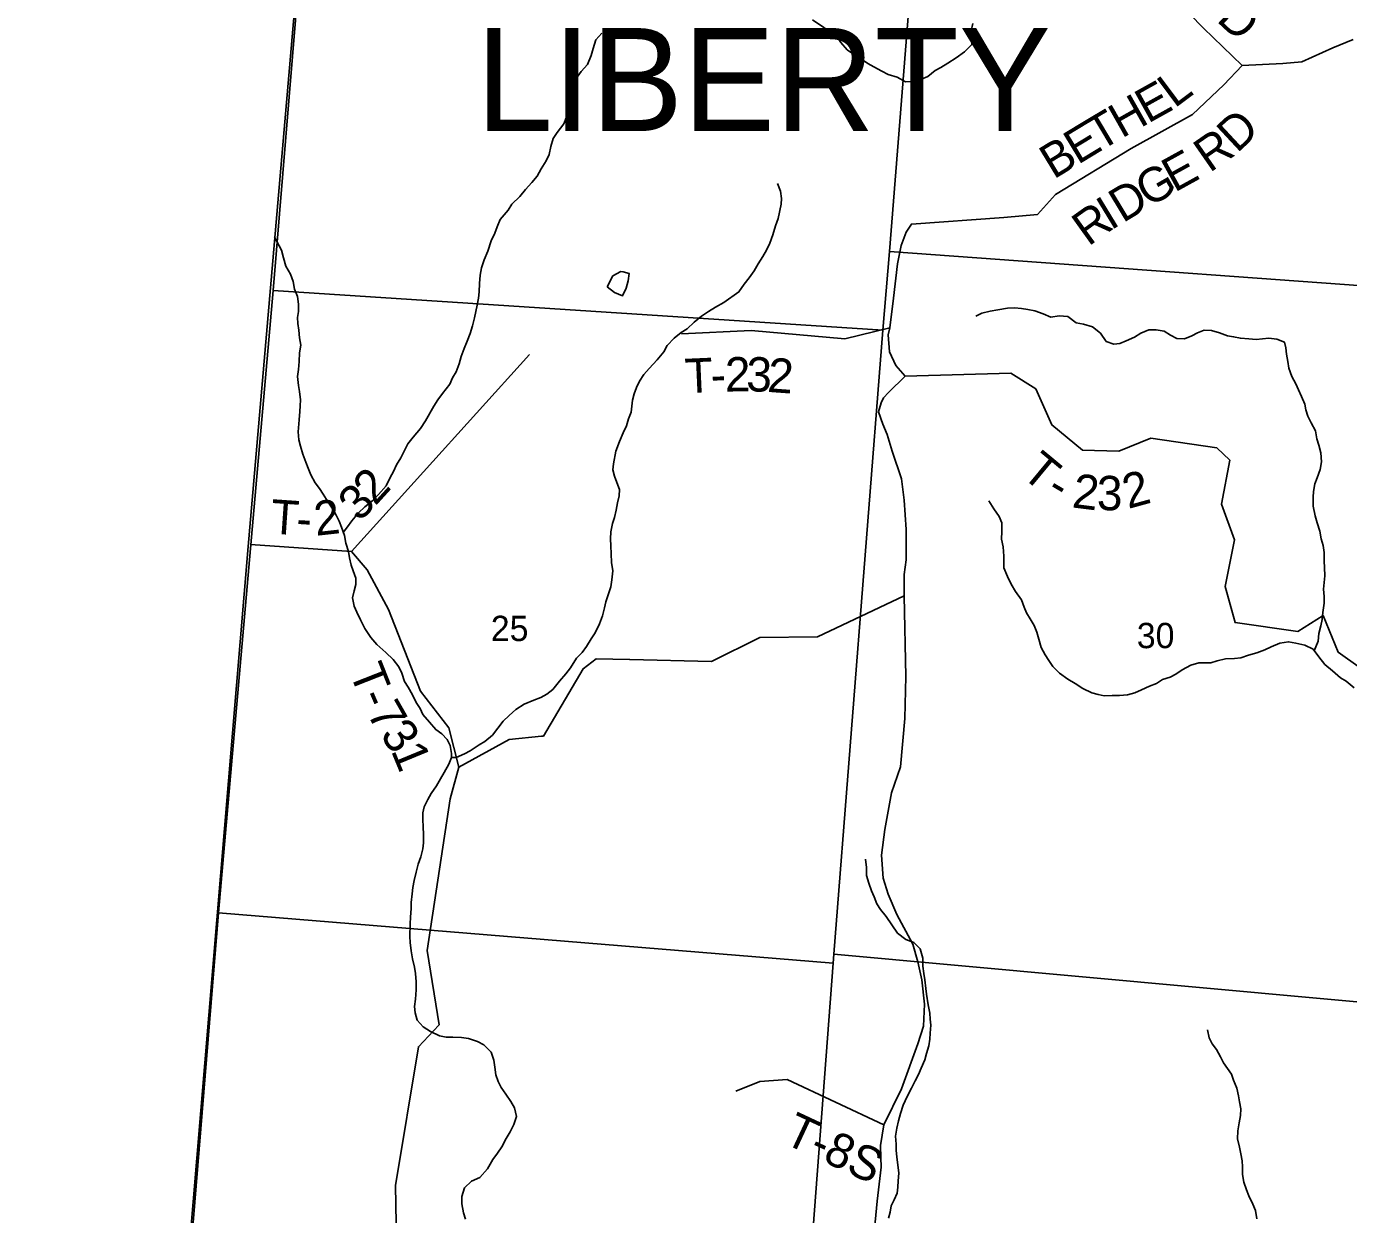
# Model space of a CAD drawing. Extents: x 1715311 to 2083412, y 146837 to 553079.
# Drawn here: x 1882063 to 1893599, y 380089 to 390456 of the extents above; entities that cross this region are included whole.
import ezdxf

# ---------------------------------------------------------------- set-up
doc = ezdxf.new("R2010")
doc.units = 0
for name, color, linetype in [('GM_X_Adjacent_County', 7, 'Continuous'), ('GM_X_County', 7, 'Continuous'), ('GM_X_County_Road', 7, 'Continuous'), ('GM_X_County_Road_Text', 7, 'Continuous'), ('GM_X_Major_River', 7, 'Continuous'), ('GM_X_Minor_Lake', 7, 'Continuous'), ('GM_X_Minor_River', 7, 'Continuous'), ('GM_X_Section', 7, 'Continuous'), ('GM_X_Section_Text', 7, 'Continuous'), ('GM_X_Township', 7, 'Continuous'), ('GM_X_Township_Road', 7, 'Continuous'), ('GM_X_Township_Road_Text', 7, 'Continuous'), ('GM_X_Township_ROW', 7, 'Continuous'), ('GM_X_Township_Text', 7, 'Continuous')]:
    doc.layers.add(name, color=color, linetype=linetype)

msp = doc.modelspace()

# ---------------------------------------------------------------- linework, layer by layer
at = {"layer": 'GM_X_Adjacent_County'}
msp.add_lwpolyline([(1886146, 409645), (1885513, 404405), (1885355, 401744), (1885146, 398934), (1884660, 393564), (1884652, 393500), (1883997, 385917), (1883278, 377323), (1883801, 377289), (1883594, 374654), (1883517, 373677), (1883386, 372010), (1883061, 368444), (1882904, 367026), (1882647, 364366), (1882063, 357591)], dxfattribs=at)
at = {"layer": 'GM_X_County'}
msp.add_lwpolyline([(1882063, 357591), (1882647, 364366), (1882904, 367026), (1883061, 368444), (1883386, 372010), (1883517, 373677), (1883594, 374654), (1883801, 377289), (1883278, 377323), (1883997, 385917), (1884652, 393500), (1884660, 393564), (1885146, 398934), (1885355, 401744), (1885513, 404405), (1886146, 409645)], dxfattribs=at)
at = {"layer": 'GM_X_County_Road'}
msp.add_lwpolyline([(1889434, 379655), (1889487, 380206), (1889521, 380502), (1889519, 380586), (1889514, 380692), (1889544, 380872), (1889698, 381185), (1889842, 381579), (1889891, 381733), (1889898, 381925), (1889875, 382137), (1889842, 382294), (1889797, 382448), (1889658, 382707), (1889583, 382886), (1889538, 383024), (1889523, 383224), (1889552, 383450), (1889612, 383768), (1889689, 383996), (1889728, 384418), (1889737, 384784), (1889721, 385488), (1889722, 385675), (1889739, 385801), (1889738, 386067), (1889720, 386322), (1889697, 386508), (1889616, 386751), (1889573, 386897), (1889535, 386987), (1889498, 387093), (1889520, 387173), (1889542, 387215), (1889585, 387263), (1889731, 387404), (1889648, 387497), (1889593, 387617), (1889581, 387764), (1889595, 387826), (1889627, 388086), (1889663, 388384), (1889695, 388546), (1889740, 388661), (1889784, 388731), (1890590, 388789), (1890886, 388816), (1891043, 388989), (1891703, 389392), (1892238, 389687), (1892509, 389948), (1892670, 390116), (1893026, 390132), (1893190, 390147), (1893460, 390269), (1893638, 390341)], dxfattribs=at)
at = {"layer": 'GM_X_Major_River'}
msp.add_lwpolyline([(1885894, 380050), (1885878, 380104), (1885863, 380182), (1885861, 380246), (1885886, 380322), (1885946, 380380), (1886018, 380413), (1886087, 380487), (1886133, 380568), (1886172, 380624), (1886212, 380680), (1886249, 380752), (1886283, 380810), (1886316, 380875), (1886338, 380945), (1886323, 381021), (1886289, 381076), (1886246, 381138), (1886206, 381198), (1886179, 381251), (1886159, 381307), (1886150, 381375), (1886140, 381437), (1886117, 381505), (1886053, 381570), (1885999, 381600), (1885920, 381625), (1885860, 381633), (1885784, 381636), (1885724, 381638), (1885668, 381649), (1885590, 381686), (1885525, 381726), (1885473, 381786), (1885456, 381849), (1885450, 381903), (1885457, 381969), (1885465, 382049), (1885464, 382121), (1885458, 382191), (1885449, 382249), (1885433, 382319), (1885420, 382391), (1885412, 382462), (1885409, 382514), (1885410, 382626), (1885414, 382684), (1885419, 382760), (1885421, 382812), (1885428, 382888), (1885434, 382942), (1885446, 383004), (1885465, 383076), (1885482, 383146), (1885504, 383211), (1885521, 383281), (1885527, 383333), (1885529, 383399), (1885526, 383479), (1885522, 383531), (1885523, 383594), (1885533, 383648), (1885566, 383711), (1885596, 383763), (1885641, 383829), (1885675, 383891), (1885707, 383946), (1885748, 384018), (1885771, 384077)], dxfattribs=at)
at = {"layer": 'GM_X_Minor_Lake'}
for points in [[(1887269, 388314), (1887248, 388319), (1887180, 388280), (1887131, 388184)], [(1887131, 388184), (1887193, 388136), (1887264, 388107), (1887295, 388171), (1887313, 388237), (1887321, 388301), (1887269, 388314)]]:
    msp.add_lwpolyline(points, dxfattribs=at)
at = {"layer": 'GM_X_Minor_River'}
for points in [[(1890321, 390482), (1890305, 390418), (1890310, 390350), (1890312, 390300), (1890249, 390234), (1890175, 390183), (1890101, 390135), (1890041, 390098), (1889991, 390072), (1889927, 390020), (1889872, 389995), (1889814, 389977), (1889733, 389974), (1889659, 390014), (1889583, 390037), (1889527, 390065), (1889458, 390103), (1889404, 390132), (1889348, 390170), (1889291, 390206), (1889223, 390253), (1889168, 390315), (1889138, 390366), (1889084, 390402), (1889021, 390448), (1888923, 390513)], [(1884827, 386041), (1884865, 386091), (1884903, 386142), (1884962, 386212), (1885016, 386264), (1885086, 386321), (1885134, 386373), (1885201, 386448), (1885237, 386520), (1885266, 386572), (1885292, 386632), (1885330, 386692), (1885391, 386815), (1885437, 386871), (1885502, 386947), (1885546, 387016), (1885617, 387142), (1885653, 387198), (1885693, 387253), (1885758, 387335), (1885782, 387389), (1885812, 387441), (1885839, 387511), (1885857, 387576), (1885883, 387646), (1885910, 387710), (1885934, 387776), (1885955, 387844), (1885973, 387914), (1885985, 387968), (1885996, 388024), (1886008, 388086), (1886014, 388140), (1886015, 388212), (1886023, 388286), (1886034, 388349), (1886058, 388421), (1886089, 388495), (1886117, 388585), (1886150, 388651), (1886170, 388709), (1886198, 388772), (1886265, 388854), (1886299, 388906), (1886369, 388971), (1886418, 389033), (1886474, 389095), (1886518, 389150), (1886555, 389214), (1886597, 389284), (1886625, 389338), (1886640, 389408), (1886660, 389478), (1886694, 389531), (1886751, 389605), (1886771, 389659), (1886788, 389727), (1886796, 389787), (1886814, 389873), (1886839, 389943), (1886859, 390002), (1886904, 390062), (1886958, 390124), (1886990, 390204), (1887007, 390264), (1887031, 390339), (1887083, 390397)], [(1885771, 384077), (1885814, 384078), (1885885, 384110), (1885935, 384135), (1886013, 384189), (1886063, 384216), (1886131, 384272), (1886224, 384395), (1886274, 384445), (1886334, 384495), (1886407, 384542), (1886489, 384576), (1886551, 384601), (1886603, 384629), (1886655, 384671), (1886713, 384742), (1886770, 384808), (1886810, 384860), (1886862, 384943), (1886913, 384993), (1886949, 385045), (1886991, 385113), (1887026, 385166), (1887062, 385244), (1887090, 385314), (1887107, 385384), (1887119, 385436), (1887138, 385496), (1887162, 385566), (1887170, 385626), (1887179, 385705), (1887169, 385778), (1887166, 385854), (1887162, 385924), (1887159, 385986), (1887161, 386046), (1887176, 386120), (1887194, 386171), (1887208, 386235), (1887221, 386299), (1887235, 386359), (1887237, 386415), (1887214, 386477), (1887194, 386532), (1887181, 386586), (1887185, 386640), (1887206, 386751), (1887238, 386835), (1887269, 386911), (1887299, 386971), (1887317, 387031), (1887340, 387089), (1887346, 387143), (1887350, 387195), (1887365, 387249), (1887385, 387306), (1887413, 387362), (1887450, 387418), (1887496, 387472), (1887566, 387547), (1887625, 387617), (1887655, 387673), (1887715, 387736), (1887777, 387786), (1887828, 387818), (1887890, 387877), (1887954, 387929), (1888014, 387970), (1888074, 388008), (1888147, 388048), (1888279, 388139), (1888325, 388206), (1888368, 388264), (1888412, 388324), (1888448, 388386), (1888487, 388449), (1888519, 388505), (1888549, 388565), (1888576, 388639), (1888598, 388715), (1888621, 388779), (1888649, 388904), (1888652, 388956), (1888642, 389018), (1888617, 389085)], [(1885771, 384077), (1885771, 384112), (1885759, 384182), (1885734, 384235), (1885688, 384285), (1885634, 384321), (1885581, 384384), (1885523, 384452), (1885498, 384504), (1885464, 384556), (1885433, 384623), (1885393, 384691), (1885363, 384741), (1885338, 384813), (1885312, 384867), (1885263, 384932), (1885199, 384994), (1885120, 385063), (1885068, 385125), (1885017, 385203), (1884978, 385278), (1884946, 385346), (1884924, 385398), (1884907, 385470), (1884923, 385532), (1884936, 385586), (1884936, 385642), (1884914, 385706), (1884897, 385756), (1884883, 385818), (1884872, 385875), (1884850, 385947), (1884837, 386015), (1884811, 386087), (1884791, 386139), (1884766, 386193), (1884738, 386243), (1884697, 386304), (1884651, 386374), (1884620, 386424), (1884582, 386475), (1884544, 386543), (1884521, 386603), (1884501, 386655), (1884474, 386723), (1884454, 386795), (1884439, 386850), (1884435, 386920), (1884444, 387024), (1884448, 387096), (1884451, 387146), (1884455, 387198), (1884445, 387272), (1884438, 387322), (1884428, 387402), (1884437, 387464), (1884443, 387532), (1884447, 387608), (1884458, 387674), (1884446, 387738), (1884439, 387806), (1884431, 387864), (1884428, 387916), (1884438, 387970), (1884438, 388034), (1884427, 388100), (1884403, 388164), (1884390, 388232), (1884366, 388294), (1884327, 388365), (1884305, 388437), (1884290, 388503), (1884228, 388617)], [(1893299, 385008), (1893333, 385093), (1893340, 385159), (1893358, 385227), (1893368, 385281), (1893373, 385343), (1893387, 385425), (1893386, 385481), (1893380, 385545), (1893393, 385661), (1893389, 385735), (1893386, 385789), (1893386, 385865), (1893377, 385927), (1893361, 385985), (1893348, 386053), (1893326, 386125), (1893306, 386187), (1893291, 386270), (1893289, 386348), (1893292, 386398), (1893304, 386466), (1893325, 386517), (1893351, 386591), (1893363, 386657), (1893358, 386735), (1893338, 386803), (1893323, 386859), (1893309, 386928), (1893272, 386998), (1893244, 387056), (1893227, 387110), (1893217, 387160), (1893189, 387228), (1893162, 387285), (1893140, 387337), (1893103, 387403), (1893077, 387475), (1893070, 387533), (1893056, 387597), (1893052, 387651), (1893041, 387701), (1892973, 387728), (1892903, 387736), (1892849, 387731), (1892793, 387725), (1892729, 387731), (1892655, 387736), (1892596, 387748), (1892542, 387757), (1892472, 387783), (1892402, 387802), (1892338, 387806), (1892280, 387784), (1892230, 387757), (1892166, 387729), (1892100, 387734), (1892045, 387762), (1891991, 387798), (1891919, 387809), (1891857, 387809), (1891787, 387780), (1891731, 387744), (1891657, 387714), (1891603, 387691), (1891551, 387685), (1891485, 387706), (1891434, 387780), (1891364, 387834), (1891286, 387859), (1891221, 387869), (1891149, 387926), (1891075, 387930), (1891001, 387919), (1890934, 387949), (1890860, 387974), (1890800, 387986), (1890746, 387994), (1890684, 388001), (1890624, 387999), (1890540, 387984), (1890472, 387972), (1890400, 387953), (1890348, 387927)], [(1891601, 384618), (1891535, 384619), (1891467, 384615), (1891415, 384626), (1891359, 384642), (1891280, 384679), (1891212, 384723), (1891149, 384761), (1891077, 384812), (1891017, 384872), (1890984, 384923), (1890952, 384973), (1890917, 385037), (1890897, 385109), (1890878, 385171), (1890856, 385229), (1890820, 385286), (1890789, 385338), (1890769, 385388), (1890744, 385454), (1890692, 385525), (1890655, 385591), (1890623, 385657), (1890592, 385731), (1890590, 385785), (1890590, 385835), (1890585, 385915), (1890571, 385981), (1890574, 386049), (1890574, 386125), (1890551, 386180), (1890503, 386246), (1890460, 386318)], [(1893648, 384685), (1893579, 384744), (1893527, 384772), (1893459, 384832), (1893392, 384889), (1893338, 384955), (1893289, 385021), (1893217, 385058), (1893139, 385074), (1893076, 385087), (1892998, 385075), (1892922, 385042), (1892868, 385016), (1892797, 384991), (1892727, 384971), (1892659, 384946), (1892603, 384940), (1892526, 384938), (1892452, 384921), (1892398, 384903), (1892346, 384902), (1892292, 384902), (1892222, 384884), (1892146, 384841), (1892093, 384805), (1892043, 384778), (1891975, 384758), (1891923, 384724), (1891863, 384701), (1891793, 384667), (1891733, 384640), (1891669, 384624), (1891601, 384618)], [(1889690, 380972), (1889713, 381044), (1889747, 381118), (1889784, 381191), (1889816, 381257), (1889846, 381311), (1889869, 381365), (1889901, 381439), (1889917, 381495), (1889936, 381562), (1889946, 381618), (1889948, 381672), (1889955, 381742), (1889947, 381794), (1889946, 381846), (1889932, 381919), (1889915, 382011), (1889911, 382061), (1889902, 382137), (1889894, 382191), (1889884, 382257), (1889883, 382325), (1889861, 382407), (1889806, 382462), (1889736, 382488), (1889663, 382545), (1889564, 382689), (1889516, 382750), (1889482, 382800), (1889461, 382862), (1889435, 382914), (1889414, 382982), (1889394, 383048), (1889393, 383116), (1889385, 383189)], [(1892799, 380053), (1892788, 380123), (1892764, 380181), (1892729, 380252), (1892707, 380304), (1892684, 380372), (1892672, 380438), (1892673, 380506), (1892669, 380558), (1892659, 380620), (1892646, 380676), (1892630, 380749), (1892633, 380819), (1892643, 380890), (1892656, 380954), (1892660, 381012), (1892648, 381073), (1892639, 381125), (1892625, 381191), (1892596, 381263), (1892578, 381313), (1892542, 381363), (1892507, 381414), (1892481, 381464), (1892446, 381528), (1892410, 381578), (1892382, 381630), (1892367, 381701)], [(1889585, 380056), (1889599, 380110), (1889609, 380166), (1889633, 380218), (1889660, 380276), (1889666, 380328), (1889670, 380384), (1889675, 380450), (1889667, 380522), (1889658, 380590), (1889652, 380650), (1889651, 380702), (1889647, 380772), (1889657, 380842), (1889672, 380908), (1889690, 380972)]]:
    msp.add_lwpolyline(points, dxfattribs=at)
at = {"layer": 'GM_X_Section'}
for points in [[(1884665, 393577), (1889966, 393194), (1889933, 392776), (1889594, 388493), (1889535, 387805), (1884215, 388153)], [(1889933, 392776), (1895398, 392411), (1895047, 388096), (1889594, 388493)], [(1889594, 388493), (1895047, 388096), (1894435, 381874), (1889109, 382362), (1889535, 387805)], [(1889535, 387805), (1889109, 382362), (1889103, 382282), (1883738, 382721), (1884215, 388153)], [(1883738, 382721), (1889103, 382282), (1888702, 376971), (1883813, 377318), (1883299, 377352)], [(1889103, 382282), (1889109, 382362), (1894435, 381874), (1894025, 376597), (1893489, 376632), (1888702, 376971)]]:
    msp.add_lwpolyline(points, close=True, dxfattribs=at)
at = {"layer": 'GM_X_Township'}
msp.add_lwpolyline([(1903813, 375878), (1902508, 375975), (1902146, 376005), (1899431, 376156), (1897767, 376287), (1897254, 376314), (1895273, 376475), (1894015, 376554), (1888519, 376950), (1885380, 377176), (1883801, 377289), (1883278, 377323), (1883997, 385917), (1884652, 393500), (1884660, 393564), (1885146, 398934), (1885355, 401744), (1885513, 404405), (1886146, 409645)], dxfattribs=at)
at = {"layer": 'GM_X_Township_Road'}
for points in [[(1892670, 390116), (1892333, 390442), (1892092, 390691), (1891806, 391227), (1891320, 391757), (1891020, 391721), (1890753, 391379), (1890619, 391424), (1890747, 391724), (1890696, 391999), (1890364, 392382), (1889888, 392633), (1889683, 392797), (1889336, 392801), (1889144, 392986)], [(1887780, 387773), (1888386, 387804), (1889203, 387731), (1889595, 387826)], [(1889731, 387404), (1890653, 387431), (1890869, 387294), (1891009, 386979), (1891276, 386759), (1891593, 386751), (1891874, 386863), (1892449, 386779), (1892564, 386671), (1892489, 386289), (1892602, 385977), (1892523, 385568), (1892608, 385255), (1893157, 385177), (1893376, 385315), (1893508, 384996), (1894254, 384463)], [(1884900, 385874), (1885528, 386569)], [(1884019, 385935), (1884900, 385874)], [(1885836, 383994), (1885749, 384335), (1885501, 384656), (1885222, 385368), (1885035, 385714), (1884900, 385874)], [(1887326, 384932), (1887327, 384932), (1888039, 384915), (1888462, 385123), (1888964, 385130), (1889721, 385488)], [(1886558, 384262), (1886558, 384262), (1886574, 384263), (1886921, 384851), (1887035, 384939), (1887326, 384932)], [(1885614, 381692), (1885615, 381693), (1885664, 381745), (1885559, 382392), (1885761, 383716), (1885836, 383994), (1886276, 384235), (1886558, 384262)], [(1885365, 377233), (1885335, 377345), (1885284, 380341), (1885483, 381553), (1885614, 381692)], [(1889544, 380872), (1888702, 381268), (1888462, 381250), (1888253, 381167)]]:
    msp.add_lwpolyline(points, dxfattribs=at)
at = {"layer": 'GM_X_Township_ROW'}
msp.add_lwpolyline([(1885528, 386569), (1885528, 386569), (1886453, 387593)], dxfattribs=at)

# ---------------------------------------------------------------- texts
at = {"layer": 'GM_X_County_Road_Text'}
for s, rotation, p in [('L', 36.7146, (1892080, 389738)), ('E', 29.065, (1891848, 389606)), ('H', 29.4661, (1891619, 389476)), ('T', 30.7874, (1891427, 389362)), ('D', 42.9819, (1892625, 389345)), ('E', 31.2526, (1891236, 389246)), ('B', 31.2656, (1891025, 389118)), ('R', 34.7931, (1892386, 389175)), ('E', 28.8752, (1892080, 389004)), ('G', 30.0029, (1891853, 388872)), ('D', 31.1412, (1891628, 388737)), ('I', 31.3359, (1891523, 388673)), ('R', 35.6107, (1891328, 388532))]:
    msp.add_text(s, height=300, rotation=rotation, dxfattribs=at).set_placement(p)
at = {"layer": 'GM_X_Section_Text'}
for s, p in [('25', (1886115, 385093)), ('30', (1891751, 385031))]:
    msp.add_text(s, height=221, rotation=0, dxfattribs=at).set_placement(p)
at = {"layer": 'GM_X_Township_Road_Text'}
for s, rotation, p in [('D', 316.9333, (1892438, 390508)), ('T', 2.495, (1887814, 387256)), ('2', 0.6557, (1888159, 387270)), ('3', 358.5688, (1888341, 387273)), ('2', 355.8591, (1888522, 387268)), ('-', 2.0145, (1888038, 387266)), ('T', 320.3261, (1890732, 386539)), ('2', 47.8267, (1885107, 386267)), ('2', 352.8894, (1891179, 386260)), ('2', 15.3595, (1891675, 386245)), ('3', 45.2859, (1884968, 386126)), ('-', 329.337, (1890947, 386366)), ('3', 359.6986, (1891402, 386235)), ('T', 356.0914, (1884186, 386032)), ('2', 6.3002, (1884589, 386011)), ('-', 356.4883, (1884412, 386017)), ('T', 291.4871, (1884877, 384828)), ('-', 293.2277, (1884963, 384610)), ('7', 299.5823, (1885028, 384465)), ('3', 306.4216, (1885141, 384271)), ('1', 292.4421, (1885241, 384139)), ('T-8S', 334.9628, (1888657, 380718))]:
    msp.add_text(s, height=300, rotation=rotation, dxfattribs=at).set_placement(p)
at = {"layer": 'GM_X_Township_Text'}
msp.add_text('LIBERTY', height=900, rotation=0, dxfattribs=at).set_placement((1885986, 389543))

doc.saveas('drawing.dxf')
